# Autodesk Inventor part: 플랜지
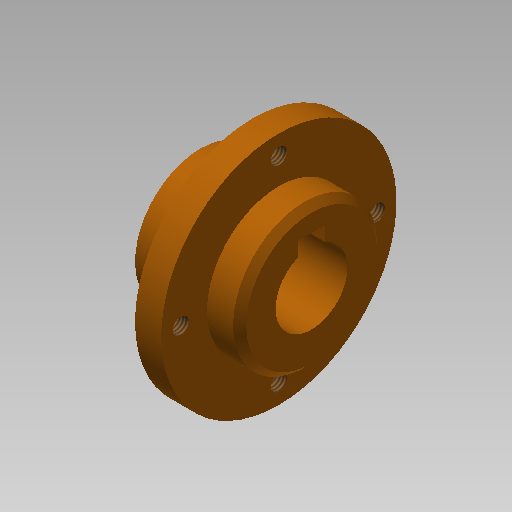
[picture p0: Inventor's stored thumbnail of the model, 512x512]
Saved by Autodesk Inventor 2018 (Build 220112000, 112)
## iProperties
Created: 2019-10
Part Number: 플랜지
Material: 스테인리스강
Document SubType Name: Modeling
Designer: mduedu
Density: 1 g/cm^3
Appearance: 주황색
Author: mduedu
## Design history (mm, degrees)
sketch "스케치1"
  geometry: L1 (0, 0)-(8, 0); L2 (8, 0)-(8, 10); L3 (8, 10)-(0, 10); L4 (0, 10)-(0, 0); L5 (8, 0)-(12, 0); L6 (12, 0)-(12, 18); L7 (12, 18)-(8, 18); L8 (8, 18)-(8, 0); L9 (12, 0)-(17, 0); L10 (17, 0)-(17, 11); L11 (17, 11)-(12, 11); L12 (12, 11)-(12, 0)
  constraints: 24 end point, 6 parallel, 3 horizontal, 3 perpendicular
  dimensions: "d0" = 17 distance between parallel lines of L10 L4; "d2" = 20 diameter of L3 L1; "d3" = 22 diameter of L11 L9; "d4" = 36 diameter of L7 L5; "d5" = 4 distance of L6.end L7.end; "d6" = 5 distance of L10.end L11.end
revolve "회전1" sketch "스케치1" stored, may be unused: angle "d7" = 90 deg
sketch "스케치2"
  geometry: L1 (-2, 5.123)-(2, 5.123); L2 (2, 5.123)-(2, 7.3); L3 (2, 7.3)-(-2, 7.3); L4 (-2, 7.3)-(-2, 5.123); A1 r 5.5 centre (0, 0) between (-2, 5.123) and (2, 5.123); 1 further point
  constraints: 8 end point, 2 parallel, 2 point on circle, 1 centre point, 1 coincident, 1 horizontal, 1 perpendicular
  dimensions: "d8" = 11 diameter of A1; "d10" = 4 distance of L2.end L3.end; "d11" = 7.3 distance from line of L3 point (0, 0)
extrude "돌출1" cut sketch "스케치2" extent not by distance; stored distance "d12" = 10; taper "d13" = 0 deg
chamfer "모따기1" distance "d14" = 1; stored, may be unused: second distance "d15" = 2, angle "d16" = 45 deg
chamfer "모따기2" distance "d17" = 1; stored, may be unused: second distance "d18" = 2, angle "d19" = 45 deg
sketch "스케치3" dims "d20" = 30
  geometry: 3 further points
  constraints: 2 vertical alignment, 1 coincident, 2 other
hole "구멍1" sketch "스케치3" at (0, 15) diameter "d21" = 2.459; stored, may be unused: countersink angle "d25" = 90 deg, drill point angle "d27" = 118 deg; dims "d22" = 6, "d23" = 4, "d24" = 2, "d26" = 8
node "솔리드1"
pattern_circular "원형 패턴1" dims angle "d29" = 360 deg
